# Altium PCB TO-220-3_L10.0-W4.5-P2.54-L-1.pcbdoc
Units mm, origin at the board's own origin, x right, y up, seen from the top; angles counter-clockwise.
Board outline 22.76 x 17.26 mm, 2 copper layers (Top Layer, Bottom Layer), stack 0 mm thick; 1 components, 0 nets, 3 pads, 0 vias.
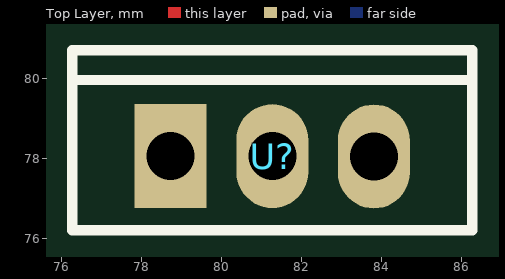
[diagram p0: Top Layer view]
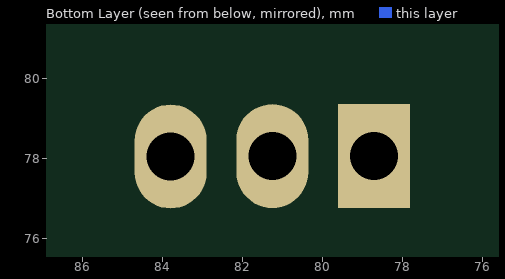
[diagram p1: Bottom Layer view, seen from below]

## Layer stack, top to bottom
Top Layer: signal copper (thickness not stored)
Bottom Layer: signal copper (thickness not stored)

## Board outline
92.61,69.85 69.85,69.85 69.85,87.115 92.61,87.115

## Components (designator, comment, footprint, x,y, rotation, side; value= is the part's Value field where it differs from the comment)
U? "" TO-220-3_L10.0-W4.5-P2.54-L-1 81.26,78.05 r0 top

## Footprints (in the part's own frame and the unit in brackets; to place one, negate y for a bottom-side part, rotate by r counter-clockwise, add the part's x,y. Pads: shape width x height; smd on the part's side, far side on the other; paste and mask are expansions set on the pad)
TO-220-3_L10.0-W4.5-P2.54-L-1 [mm]
  rect 1.8x2.6 hole 1.2: 1(-2.54,0.005)
  oval 1.8x2.6 hole 1.2: 2(0,0.005)
  oval 1.8x2.6 hole 1.2 copper offset 0,0: 3(2.54,-0.005)
  silkscreen extent -5,-1.85 5,2.65

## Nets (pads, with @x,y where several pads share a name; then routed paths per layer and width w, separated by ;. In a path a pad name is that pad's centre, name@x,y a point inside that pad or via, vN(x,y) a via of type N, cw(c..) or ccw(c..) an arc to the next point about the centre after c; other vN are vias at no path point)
pads on no net: U?.1 U?.2 U?.3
